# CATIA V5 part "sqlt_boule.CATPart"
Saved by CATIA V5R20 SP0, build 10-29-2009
Part number: sqlt_boule
Publications: "Plan.1", "Point.1", "Droite.1", "Point.2", "Point.3", "Point.4", "Plan.2", "Point.5", "Point.6", "Droite.2", "Plan.3", "rayon_boule"
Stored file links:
  D:\ecole\thinkmotion\sqlt_boule.CATPart
  D:\ecole\thinkmotion\sqlt_eolienne.CATProduct
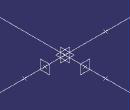
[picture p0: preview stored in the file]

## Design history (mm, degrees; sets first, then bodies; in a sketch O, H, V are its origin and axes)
External parameters (linked from other documents)
  External.profondeur_trou = 25 mm
  `External.profondeur_perçage` = 25 mm
Body1 (main body)
  Plane1: type Offset, RefPlane xy-plane, Offset 0
  Point1: (0, 0, 0)
  Line1: type PtDir, RefPoint Point1, Direction yz-plane, Start 0, End 20
  Point2: (50 {= `External.profondeur_perçage` *2}, 0, 0)
  Point3: (-50 {= -`External.profondeur_perçage` *2}, 0, 0)
  Point4: (25 {= `External.profondeur_perçage`}, 0, 0)
  Plane2: type Normal, Curve Line1, RefPoint Point4
  Point5: (0, 50 {= `External.profondeur_perçage` *2}, 0)
  Point6: (0, 25 {= External.profondeur_trou}, 0)
  Line2: type PtPt, FirstPoint Point1, SecondPoint Point5
  Plane3: type Normal, Curve Line2, RefPoint Point6
  Plane4: type Offset, RefPlane yz-plane, Offset 0
  Plane5: type Offset, RefPlane zx-plane, Offset 0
